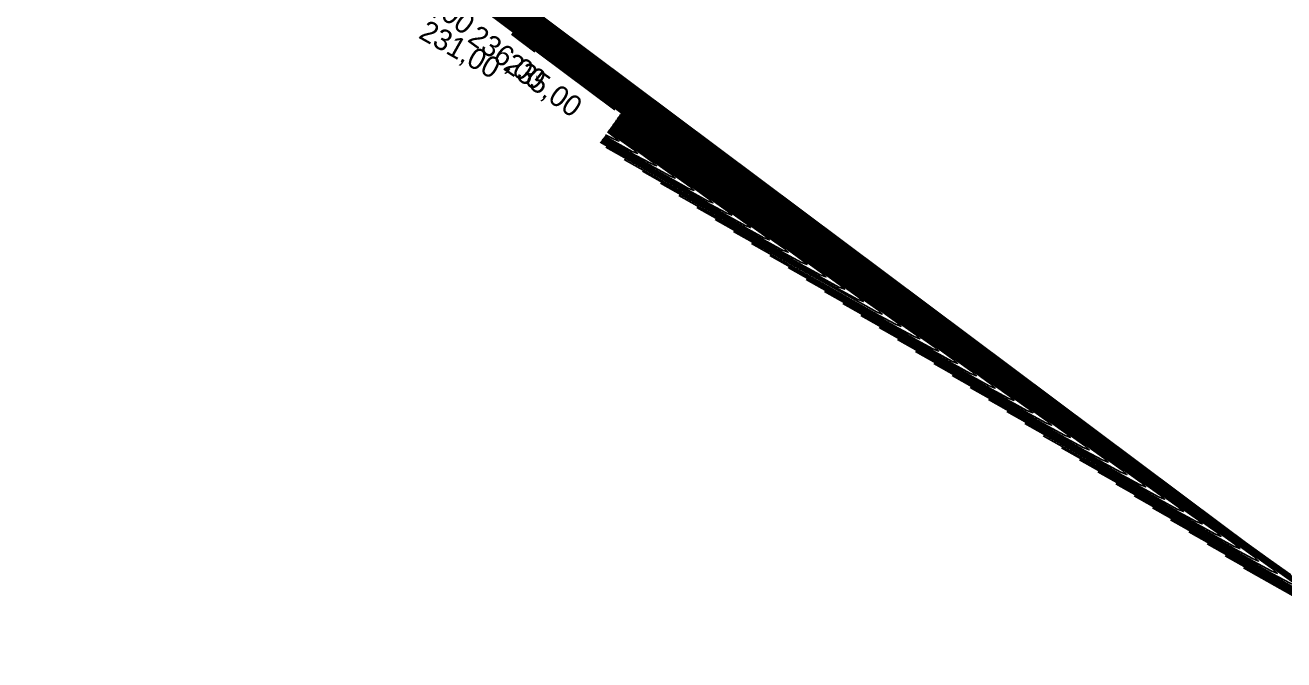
# Model space of a CAD drawing. Extents: x -500397 to -496810, y -1135552 to -1132176.
# Drawn here: x -500036.9 to -499917.1, y -1135074.6 to -1135014.2 of the extents above; entities that cross this region are included whole.
import ezdxf

# ---------------------------------------------------------------- set-up
doc = ezdxf.new("R2010")
doc.units = 0
doc.layers.add('30', color=7, linetype='Continuous')
doc.layers.add('40', color=7, linetype='Continuous')

msp = doc.modelspace()

# ---------------------------------------------------------------- linework, layer by layer
at = {"layer": '30'}
for points in [[(-500064.51, -1134956.12), (-499924.61, -1135060.7), (-499922.49, -1135062.28), (-499920.35, -1135063.83), (-499918.2, -1135065.37), (-499916.04, -1135066.89), (-499907.25, -1135073.01), (-499905.68, -1135074.14), (-499905.2, -1135074.58), (-499905.81, -1135074.34), (-499907.51, -1135073.42), (-499920.96, -1135065.84)], [(-500064.66, -1134956.33), (-499928.05, -1135058.46), (-499925.94, -1135060.02), (-499923.82, -1135061.56), (-499921.68, -1135063.09), (-499919.54, -1135064.6), (-499910.81, -1135070.67), (-499909.25, -1135071.79), (-499908.78, -1135072.23), (-499909.38, -1135072), (-499911.07, -1135071.08), (-499924.43, -1135063.55)], [(-499922.7, -1135064.69), (-499909.29, -1135072.25), (-499907.6, -1135073.17), (-499906.99, -1135073.41), (-499907.47, -1135072.96), (-499909.03, -1135071.84), (-499917.79, -1135065.74), (-499919.94, -1135064.23), (-499922.08, -1135062.7), (-499924.21, -1135061.15), (-499926.33, -1135059.58), (-500064.59, -1134956.23)], [(-500063.12, -1134957), (-499922.89, -1135061.83), (-499920.76, -1135063.41), (-499918.61, -1135064.97), (-499916.46, -1135066.51)], [(-499926.16, -1135062.41), (-499912.85, -1135069.91), (-499911.17, -1135070.82), (-499910.57, -1135071.06), (-499911.04, -1135070.62), (-499912.59, -1135069.5), (-499921.29, -1135063.45), (-499923.43, -1135061.95), (-499925.55, -1135060.43), (-499927.67, -1135058.89), (-499929.77, -1135057.33), (-500054.42, -1134964.15)], [(-499929.63, -1135060.12), (-499916.41, -1135067.57), (-499914.75, -1135068.47), (-499914.15, -1135068.71), (-499914.62, -1135068.27), (-499916.16, -1135067.16), (-499924.79, -1135061.16), (-499926.91, -1135059.66), (-499929.02, -1135058.16), (-499931.12, -1135056.63), (-499933.21, -1135055.08), (-500051.13, -1134966.93)], [(-500051.06, -1134966.83), (-499931.49, -1135056.21), (-499929.39, -1135057.76), (-499927.29, -1135059.29), (-499925.17, -1135060.81), (-499923.04, -1135062.3), (-499914.38, -1135068.33), (-499912.83, -1135069.44), (-499912.36, -1135069.88), (-499912.96, -1135069.65), (-499914.63, -1135068.74), (-499927.89, -1135061.27)], [(-499931.36, -1135058.98), (-499918.2, -1135066.4), (-499916.53, -1135067.3), (-499915.94, -1135067.53), (-499916.41, -1135067.1), (-499917.94, -1135065.99), (-499926.54, -1135060.01), (-499928.66, -1135058.52), (-499930.76, -1135057.02), (-499932.85, -1135055.5), (-499934.93, -1135053.96), (-500051.21, -1134967.03)], [(-500041.04, -1134974.96), (-499938.37, -1135051.71), (-499936.3, -1135053.24), (-499934.23, -1135054.75), (-499932.14, -1135056.24), (-499930.04, -1135057.72), (-499921.51, -1135063.66), (-499919.98, -1135064.75), (-499919.52, -1135065.19), (-499920.11, -1135064.95), (-499921.76, -1135064.06), (-499934.83, -1135056.7)], [(-500040.97, -1134974.85), (-499936.65, -1135052.84), (-499934.58, -1135054.37), (-499932.49, -1135055.88), (-499930.4, -1135057.38), (-499928.29, -1135058.86), (-499919.72, -1135064.83), (-499918.2, -1135065.93), (-499917.73, -1135066.36), (-499918.32, -1135066.13), (-499919.98, -1135065.23), (-499933.09, -1135057.84)], [(-499936.56, -1135055.55), (-499923.54, -1135062.89), (-499921.9, -1135063.78), (-499921.31, -1135064.01), (-499921.77, -1135063.58), (-499923.29, -1135062.49), (-499931.79, -1135056.57), (-499933.88, -1135055.1), (-499935.96, -1135053.61), (-499938.03, -1135052.11), (-499940.08, -1135050.59), (-500034.24, -1134980.2)], [(-500030.88, -1134982.88), (-499941.8, -1135049.46), (-499939.76, -1135050.98), (-499937.7, -1135052.48), (-499935.63, -1135053.96), (-499933.54, -1135055.42), (-499925.07, -1135061.32), (-499923.56, -1135062.41), (-499923.1, -1135062.84), (-499923.69, -1135062.61), (-499925.32, -1135061.72), (-499938.29, -1135054.41)], [(-499943.49, -1135050.98), (-499930.67, -1135058.21), (-499929.05, -1135059.09), (-499928.47, -1135059.31), (-499928.93, -1135058.89), (-499930.42, -1135057.81), (-499938.79, -1135051.98), (-499940.86, -1135050.54), (-499942.9, -1135049.07), (-499944.94, -1135047.59), (-499946.96, -1135046.09), (-500027.67, -1134985.76)], [(-499941.76, -1135052.12), (-499928.89, -1135059.38), (-499927.26, -1135060.26), (-499926.68, -1135060.49), (-499927.14, -1135060.06), (-499928.64, -1135058.98), (-499937.04, -1135053.13), (-499939.11, -1135051.68), (-499941.17, -1135050.21), (-499943.21, -1135048.72), (-499945.24, -1135047.22), (-500027.59, -1134985.66)], [(-500027.51, -1134985.55), (-499943.52, -1135048.34), (-499941.48, -1135049.85), (-499939.43, -1135051.34), (-499937.37, -1135052.82), (-499935.29, -1135054.28), (-499926.85, -1135060.15), (-499925.35, -1135061.23), (-499924.89, -1135061.66), (-499925.47, -1135061.43), (-499927.1, -1135060.55), (-499940.02, -1135053.27)], [(-499945.22, -1135049.84), (-499932.45, -1135057.04), (-499930.84, -1135057.91), (-499930.26, -1135058.14), (-499930.71, -1135057.72), (-499932.2, -1135056.64), (-499940.55, -1135050.84), (-499942.6, -1135049.4), (-499944.64, -1135047.94), (-499946.67, -1135046.46), (-499948.68, -1135044.97), (-500017.42, -1134993.58)], [(-500014.06, -1134996.26), (-499950.4, -1135043.84), (-499948.39, -1135045.33), (-499946.37, -1135046.8), (-499944.34, -1135048.26), (-499942.3, -1135049.69), (-499933.99, -1135055.48), (-499932.5, -1135056.54), (-499932.05, -1135056.96), (-499932.63, -1135056.74), (-499934.23, -1135055.87), (-499946.95, -1135048.7)], [(-499948.69, -1135047.55), (-499936.01, -1135054.7), (-499934.41, -1135055.57), (-499933.84, -1135055.79), (-499934.29, -1135055.37), (-499935.77, -1135054.31), (-499944.05, -1135048.55), (-499946.08, -1135047.11), (-499948.11, -1135045.67), (-499950.12, -1135044.2), (-499952.12, -1135042.72), (-500010.7, -1134998.93)], [(-499950.42, -1135046.41), (-499937.79, -1135053.53), (-499936.2, -1135054.39), (-499935.63, -1135054.62), (-499936.08, -1135054.2), (-499937.55, -1135053.14), (-499945.8, -1135047.4), (-499947.83, -1135045.97), (-499949.84, -1135044.53), (-499951.85, -1135043.07), (-499953.84, -1135041.6), (-500007.33, -1135001.61)], [(-499955.62, -1135042.98), (-499943.14, -1135050.02), (-499941.56, -1135050.87), (-499941, -1135051.09), (-499941.44, -1135050.68), (-499942.9, -1135049.63), (-499951.05, -1135043.96), (-499953.06, -1135042.55), (-499955.05, -1135041.13), (-499957.03, -1135039.68), (-499959, -1135038.22), (-500004.13, -1135004.49)], [(-500004.05, -1135004.39), (-499957.28, -1135039.35), (-499955.3, -1135040.81), (-499953.31, -1135042.26), (-499951.31, -1135043.69), (-499949.3, -1135045.11), (-499941.12, -1135050.8), (-499939.66, -1135051.85), (-499939.21, -1135052.27), (-499939.78, -1135052.04), (-499941.36, -1135051.19), (-499953.89, -1135044.13)], [(-500003.97, -1135004.28), (-499955.56, -1135040.47), (-499953.58, -1135041.94), (-499951.58, -1135043.4), (-499949.57, -1135044.83), (-499947.55, -1135046.25), (-499939.33, -1135051.97), (-499937.87, -1135053.03), (-499937.42, -1135053.44), (-499937.99, -1135053.22), (-499939.58, -1135052.36), (-499952.15, -1135045.27)], [(-499957.35, -1135041.84), (-499944.92, -1135048.85), (-499943.35, -1135049.7), (-499942.79, -1135049.92), (-499943.23, -1135049.51), (-499944.68, -1135048.46), (-499952.8, -1135042.81), (-499954.8, -1135041.41), (-499956.78, -1135039.99), (-499958.76, -1135038.55), (-499960.72, -1135037.1), (-499993.88, -1135012.31)], [(-499988.37, -1135016.76), (-499990.6, -1135015.09)], [(-499990.52, -1135014.99), (-499980.76, -1135022.28)], [(-499988.23, -1135019.12), (-499988.25, -1135019.1)], [(-499967.75, -1135034.99), (-499955.61, -1135041.83), (-499954.08, -1135042.66), (-499953.53, -1135042.87), (-499953.96, -1135042.47), (-499955.38, -1135041.45), (-499963.3, -1135035.93), (-499965.25, -1135034.56), (-499967.19, -1135033.18), (-499969.12, -1135031.78), (-499971.04, -1135030.36), (-499980.62, -1135023.19)], [(-499980.54, -1135023.09), (-499969.32, -1135031.48), (-499967.39, -1135032.91), (-499965.46, -1135034.31), (-499963.51, -1135035.71), (-499961.55, -1135037.08), (-499953.59, -1135042.62), (-499952.17, -1135043.64), (-499951.74, -1135044.05), (-499952.29, -1135043.83), (-499953.83, -1135043), (-499966.02, -1135036.13)], [(-499980.47, -1135022.98), (-499967.6, -1135032.6), (-499965.67, -1135034.04), (-499963.72, -1135035.45), (-499961.77, -1135036.85), (-499959.8, -1135038.23), (-499951.81, -1135043.79), (-499950.39, -1135044.82), (-499949.95, -1135045.22), (-499950.5, -1135045), (-499952.05, -1135044.17), (-499964.28, -1135037.27)], [(-499980.39, -1135022.88), (-499965.88, -1135033.73), (-499963.94, -1135035.16), (-499961.99, -1135036.58), (-499960.03, -1135037.99), (-499958.05, -1135039.37), (-499950.03, -1135044.96), (-499948.6, -1135045.99), (-499948.16, -1135046.39), (-499948.72, -1135046.18), (-499950.27, -1135045.34), (-499962.55, -1135038.41)], [(-499960.82, -1135039.56), (-499948.48, -1135046.51), (-499946.93, -1135047.35), (-499946.37, -1135047.57), (-499946.81, -1135047.16), (-499948.25, -1135046.13), (-499956.3, -1135040.52), (-499958.28, -1135039.13), (-499960.25, -1135037.72), (-499962.21, -1135036.29), (-499964.16, -1135034.85), (-499980.32, -1135022.77)], [(-499980.24, -1135022.67), (-499962.44, -1135035.98), (-499960.48, -1135037.42), (-499958.52, -1135038.85), (-499956.54, -1135040.27), (-499954.55, -1135041.67), (-499946.46, -1135047.3), (-499945.02, -1135048.33), (-499944.58, -1135048.74), (-499945.14, -1135048.52), (-499946.7, -1135047.68), (-499959.08, -1135040.7)], [(-499981.24, -1135024.08), (-499980.94, -1135024.3), (-499979.06, -1135025.62), (-499971.42, -1135030.93), (-499970.06, -1135031.92), (-499969.64, -1135032.3), (-499970.17, -1135032.09), (-499971.65, -1135031.29), (-499982.15, -1135025.37)], [(-499981.28, -1135024.14), (-499980.81, -1135024.47), (-499973.2, -1135029.77), (-499971.85, -1135030.74), (-499971.43, -1135031.13), (-499971.96, -1135030.92), (-499973.43, -1135030.12), (-499982.07, -1135025.25)], [(-499981.99, -1135025.13), (-499975.21, -1135028.95), (-499973.75, -1135029.75), (-499973.22, -1135029.95), (-499973.63, -1135029.57), (-499974.99, -1135028.6), (-499981.32, -1135024.19)], [(-499981.35, -1135024.24), (-499976.77, -1135027.43), (-499975.42, -1135028.4), (-499975.01, -1135028.78), (-499975.53, -1135028.57), (-499976.99, -1135027.78), (-499981.9, -1135025.02)], [(-499981.39, -1135024.29), (-499978.55, -1135026.26), (-499977.21, -1135027.22), (-499976.8, -1135027.6), (-499977.32, -1135027.4), (-499978.77, -1135026.61), (-499981.82, -1135024.9)], [(-499981.73, -1135024.78), (-499980.55, -1135025.44), (-499979.11, -1135026.23), (-499978.59, -1135026.43), (-499979, -1135026.05), (-499980.33, -1135025.09), (-499981.42, -1135024.33)], [(-499981.64, -1135024.65), (-499980.9, -1135025.05), (-499980.38, -1135025.26), (-499980.79, -1135024.88), (-499981.46, -1135024.39)], [(-499981.61, -1135025.84), (-499969.86, -1135032.46), (-499968.38, -1135033.27), (-499967.85, -1135033.48), (-499968.27, -1135033.09), (-499969.64, -1135032.1), (-499977.31, -1135026.76), (-499979.2, -1135025.44), (-499981.07, -1135024.1), (-499981.19, -1135024.01)], [(-499979.88, -1135026.99), (-499968.08, -1135033.63), (-499966.59, -1135034.44), (-499966.06, -1135034.65), (-499966.48, -1135034.26), (-499967.86, -1135033.27), (-499975.56, -1135027.91), (-499977.45, -1135026.58), (-499979.34, -1135025.23), (-499981.13, -1135023.93)], [(-499981.06, -1135023.83), (-499979.48, -1135025), (-499977.6, -1135026.37), (-499975.71, -1135027.72), (-499973.81, -1135029.06), (-499966.07, -1135034.44), (-499964.69, -1135035.43), (-499964.27, -1135035.83), (-499964.81, -1135035.62), (-499966.3, -1135034.8), (-499978.14, -1135028.13)], [(-499980.99, -1135023.72), (-499979.63, -1135024.74), (-499977.76, -1135026.13), (-499975.87, -1135027.5), (-499973.97, -1135028.86), (-499972.06, -1135030.2), (-499964.29, -1135035.61), (-499962.9, -1135036.61), (-499962.48, -1135037), (-499963.02, -1135036.79), (-499964.52, -1135035.97), (-499976.41, -1135029.27)], [(-499980.92, -1135023.62), (-499977.91, -1135025.86), (-499976.03, -1135027.26), (-499974.13, -1135028.64), (-499972.23, -1135030), (-499970.31, -1135031.35), (-499962.51, -1135036.78), (-499961.12, -1135037.78), (-499960.69, -1135038.17), (-499961.23, -1135037.96), (-499962.74, -1135037.14), (-499974.68, -1135030.42)], [(-499980.84, -1135023.51), (-499976.19, -1135026.98), (-499974.3, -1135028.39), (-499972.4, -1135029.77), (-499970.48, -1135031.14), (-499968.56, -1135032.5), (-499960.73, -1135037.95), (-499959.33, -1135038.95), (-499958.9, -1135039.35), (-499959.44, -1135039.14), (-499960.96, -1135038.31), (-499972.95, -1135031.56)], [(-499980.77, -1135023.41), (-499974.47, -1135028.11), (-499972.57, -1135029.52), (-499970.66, -1135030.91), (-499968.74, -1135032.28), (-499966.81, -1135033.64), (-499958.94, -1135039.11), (-499957.54, -1135040.12), (-499957.11, -1135040.52), (-499957.66, -1135040.31), (-499959.17, -1135039.48), (-499971.21, -1135032.7)], [(-499969.48, -1135033.84), (-499957.39, -1135040.65), (-499955.87, -1135041.48), (-499955.32, -1135041.7), (-499955.75, -1135041.3), (-499957.16, -1135040.28), (-499965.05, -1135034.79), (-499967, -1135033.42), (-499968.93, -1135032.04), (-499970.85, -1135030.65), (-499972.75, -1135029.23), (-499980.69, -1135023.3)]]:
    msp.add_lwpolyline(points, dxfattribs=at)

# ---------------------------------------------------------------- texts
at = {"layer": '40'}
for s, rotation, p in [('238,00', 323.2207, (-500001.62, -1135010.36)), ('231,00', 330.5971, (-499999.54, -1135015.39)), ('236,00', 323.8569, (-499994.88, -1135015.71)), ('235,00', 324.7979, (-499991.49, -1135018.38))]:
    msp.add_text(s, height=2, rotation=rotation, dxfattribs=at).set_placement(p)

doc.saveas('drawing.dxf')
